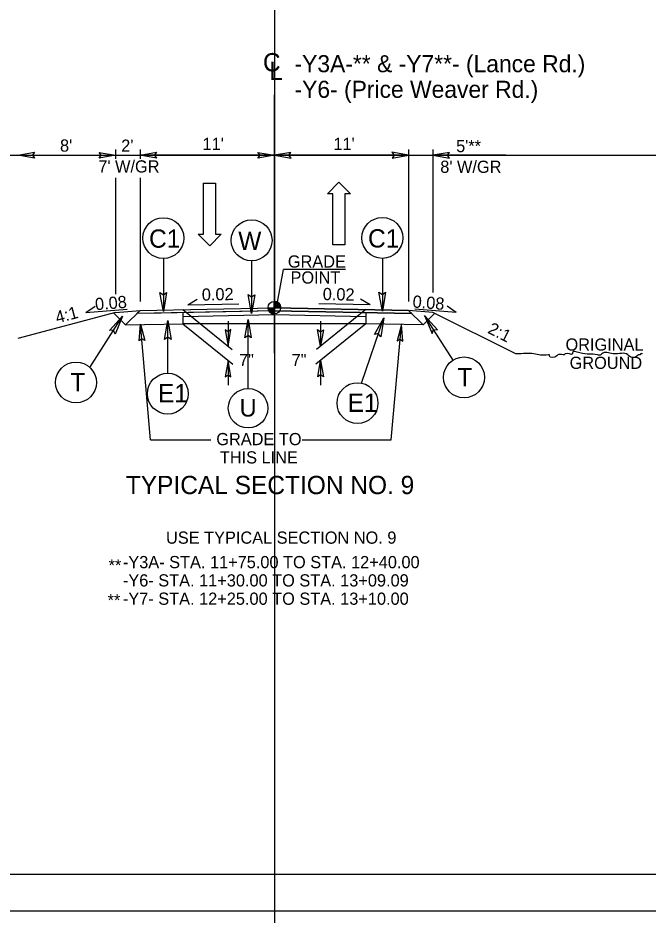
# Model space of a CAD drawing. Extents: x 18938 to 19565, y 6931 to 7973.
# Drawn here: x 19230.5 to 19282.1, y 7371.6 to 7445.2 of the extents above; entities that cross this region are included whole.
import ezdxf

# ---------------------------------------------------------------- set-up
doc = ezdxf.new("R2010")
doc.units = 0
for name, color, linetype in [('Old_Level_11', 7, 'Continuous'), ('Old_Level_2', 7, 'Continuous'), ('Old_Level_3', 7, 'Continuous'), ('Prop Dimension', 7, 'Continuous'), ('Prop Pavement Schedule Description CELL', 7, 'Continuous'), ('Prop Shade Medium', 7, 'Continuous'), ('Prop Terminator CELL', 7, 'Continuous'), ('Sheet Data Field CELL', 7, 'Continuous'), ('Sheet Plot Border Outside CELL', 7, 'Continuous'), ('Sheet Typical CELL', 7, 'Continuous'), ('Typical Curb CELL', 7, 'Continuous'), ('Typical Detail Wedge1 CELL', 7, 'Continuous'), ('Typical Detail Wedge2 CELL', 7, 'Continuous'), ('Typical Detail Wedge3 CELL', 7, 'Continuous'), ('Typical Guardrail CELL', 7, 'Continuous'), ('Typical Hinge Slope Arterial CELL', 7, 'Continuous'), ('Typical ID Circle CELL', 7, 'Continuous'), ('Typical Pavement Slope Information CELL', 7, 'Continuous'), ('Typical Shoulder Slope Information CELL', 7, 'Continuous'), ('Typical Terminator CELL', 7, 'Continuous'), ('Typical Text General CELL', 7, 'Continuous'), ('Typical Text Grade Point CELL', 7, 'Continuous'), ('Typical Text ID Circle CELL', 7, 'Continuous'), ('Typical Text Label CELL', 7, 'Continuous')]:
    doc.layers.add(name, color=color, linetype=linetype)

msp = doc.modelspace()

# ---------------------------------------------------------------- linework, layer by layer
at = {"layer": 'Old_Level_3'}
msp.add_line((19238.512, 7433.94), (19240.512, 7433.94), dxfattribs=at)
at = {"layer": 'Prop Dimension'}
msp.add_lwpolyline([(19155.167, 7371.975), (19382.434, 7371.975), (19382.434, 7518.408), (19155.167, 7518.408)], close=True, dxfattribs=at)
at = {"layer": 'Prop Pavement Schedule Description CELL'}
for p, q in [((19240.512, 7421.215), (19251.513, 7421.435)), ((19262.512, 7421.215), (19251.512, 7421.435)), ((19239.322, 7420.024), (19238.338, 7421.008)), ((19238.512, 7421.055), (19240.512, 7421.215)), ((19239.322, 7420.024), (19240.512, 7421.215)), ((19251.513, 7421.185), (19240.257, 7420.96)), ((19251.513, 7421.185), (19262.767, 7420.96)), ((19264.512, 7421.055), (19262.512, 7421.215)), ((19263.703, 7420.024), (19262.512, 7421.215)), ((19263.703, 7420.024), (19264.66, 7420.981)), ((19271.314, 7417.654), (19264.512, 7421.055)), ((19239.322, 7420.024), (19244.012, 7420.118)), ((19244.012, 7420.122), (19244.012, 7420.118)), ((19259.012, 7420.122), (19259.012, 7420.118)), ((19263.703, 7420.024), (19259.012, 7420.118))]:
    msp.add_line(p, q, dxfattribs=at)
at = {"layer": 'Prop Shade Medium'}
msp.add_line((19238.512, 7421.055), (19230.512, 7418.906), dxfattribs=at)
at = {"layer": 'Sheet Data Field CELL'}
for points in [[(19231.862, 7433.707), (19230.512, 7433.94), (19231.87, 7434.18), (19231.697, 7433.94)], [(19237.162, 7434.172), (19238.512, 7433.94), (19237.155, 7433.7), (19237.327, 7433.94)], [(19237.162, 7434.172), (19238.512, 7433.94), (19237.155, 7433.7), (19237.327, 7433.94)], [(19241.862, 7433.707), (19240.512, 7433.94), (19241.87, 7434.18), (19241.697, 7433.94)], [(19250.177, 7434.172), (19251.527, 7433.94), (19250.17, 7433.7), (19250.342, 7433.94)], [(19252.877, 7434.172), (19251.527, 7433.94), (19252.885, 7433.7), (19252.712, 7433.94)], [(19261.162, 7433.707), (19262.512, 7433.94), (19261.155, 7434.18), (19261.327, 7433.94)], [(19265.862, 7434.172), (19264.512, 7433.94), (19265.87, 7433.7), (19265.697, 7433.94)], [(19240.43, 7418.711), (19240.546, 7420.076), (19240.902, 7418.744), (19240.648, 7418.895)], [(19262.038, 7418.684), (19261.924, 7420.049), (19261.567, 7418.718), (19261.821, 7418.869)], [(19247.49, 7419.634), (19247.722, 7418.284), (19247.962, 7419.642), (19247.722, 7419.469)], [(19255.535, 7419.634), (19255.303, 7418.284), (19255.063, 7419.642), (19255.303, 7419.469)], [(19255.535, 7419.634), (19255.303, 7418.284), (19255.063, 7419.642), (19255.303, 7419.469)], [(19247.954, 7415.768), (19247.721, 7417.118), (19247.481, 7415.76), (19247.721, 7415.933)], [(19255.071, 7415.768), (19255.303, 7417.118), (19255.543, 7415.76), (19255.303, 7415.933)], [(19255.071, 7415.768), (19255.303, 7417.118), (19255.543, 7415.76), (19255.303, 7415.933)]]:
    msp.add_lwpolyline(points, close=True, dxfattribs=at)
at = {"layer": 'Sheet Typical CELL'}
for p, q in [((19230.512, 7433.94), (19238.512, 7433.94)), ((19238.512, 7434.4), (19238.512, 7433.64)), ((19240.512, 7434.4), (19240.512, 7433.64)), ((19262.512, 7433.94), (19240.512, 7433.94)), ((19262.512, 7434.4), (19262.512, 7421.955)), ((19264.512, 7434.4), (19264.512, 7422.672)), ((19270.482, 7433.94), (19264.512, 7433.94)), ((19238.512, 7432.078), (19238.512, 7422.554)), ((19240.512, 7432.086), (19240.512, 7421.955)), ((19244.013, 7421.289), (19248.068, 7418.004)), ((19259.012, 7421.289), (19254.957, 7418.004)), ((19259.012, 7421.289), (19254.957, 7418.004)), ((19241.365, 7410.59), (19240.546, 7420.076)), ((19244.013, 7420.122), (19248.118, 7416.797)), ((19247.722, 7420.328), (19247.722, 7418.284)), ((19259.012, 7420.122), (19254.907, 7416.797)), ((19259.012, 7420.122), (19254.907, 7416.797)), ((19255.303, 7420.328), (19255.303, 7418.284)), ((19255.303, 7420.328), (19255.303, 7418.284)), ((19261.097, 7410.59), (19261.924, 7420.049)), ((19247.721, 7417.118), (19247.721, 7415.094)), ((19255.303, 7417.118), (19255.303, 7415.094)), ((19255.303, 7417.118), (19255.303, 7415.094)), ((19241.365, 7410.59), (19246.325, 7410.59)), ((19253.803, 7410.59), (19261.097, 7410.59))]:
    msp.add_line(p, q, dxfattribs=at)
at = {"layer": 'Typical Curb CELL'}
msp.add_spline([(19281.678, 7417.654), (19281.506, 7417.654), (19281.506, 7417.568), (19281.335, 7417.568), (19281.25, 7417.483), (19280.564, 7417.483), (19280.479, 7417.568), (19279.279, 7417.654), (19278.337, 7417.654), (19278.252, 7417.568), (19277.995, 7417.568), (19276.539, 7417.74), (19275.939, 7417.74), (19275.939, 7417.654), (19275.34, 7417.654), (19275.254, 7417.568), (19275.168, 7417.568), (19274.74, 7417.568), (19274.654, 7417.483), (19274.055, 7417.483), (19274.055, 7417.568), (19273.969, 7417.568), (19272.77, 7417.654), (19271.399, 7417.654), (19271.314, 7417.654)], degree=3, dxfattribs=at)
at = {"layer": 'Typical Detail Wedge1 CELL'}
for p, q in [((19251, 7421.435), (19251.513, 7421.435)), ((19251.512, 7420.922), (19251.513, 7421.435)), ((19251.513, 7421.435), (19251.512, 7420.922)), ((19251.513, 7421.435), (19251.513, 7421.946)), ((19252.024, 7421.435), (19251.513, 7421.435))]:
    msp.add_line(p, q, dxfattribs=at)
for points in [[(19251.003, 7421.435), (19251.003, 7421.379)], [(19251.014, 7421.435), (19251.014, 7421.319)], [(19251.024, 7421.435), (19251.024, 7421.281)], [(19251.034, 7421.435), (19251.034, 7421.252)], [(19251.044, 7421.435), (19251.044, 7421.227)], [(19251.054, 7421.435), (19251.054, 7421.205)], [(19251.065, 7421.435), (19251.065, 7421.186)], [(19251.075, 7421.435), (19251.075, 7421.168)], [(19251.085, 7421.435), (19251.085, 7421.152)], [(19251.096, 7421.435), (19251.096, 7421.137)], [(19251.106, 7421.435), (19251.106, 7421.124)], [(19251.116, 7421.435), (19251.116, 7421.111)], [(19251.126, 7421.435), (19251.126, 7421.098)], [(19251.137, 7421.435), (19251.137, 7421.087)], [(19251.147, 7421.435), (19251.147, 7421.076)], [(19251.157, 7421.435), (19251.157, 7421.066)], [(19251.167, 7421.435), (19251.167, 7421.056)], [(19251.178, 7421.435), (19251.177, 7421.047)], [(19251.188, 7421.435), (19251.188, 7421.039)], [(19251.198, 7421.435), (19251.198, 7421.03)], [(19251.208, 7421.435), (19251.208, 7421.023)], [(19251.218, 7421.435), (19251.218, 7421.015)], [(19251.229, 7421.435), (19251.228, 7421.008)], [(19251.239, 7421.435), (19251.239, 7421.002)], [(19251.249, 7421.435), (19251.249, 7420.995)], [(19251.259, 7421.435), (19251.259, 7420.989)], [(19251.269, 7421.435), (19251.269, 7420.984)], [(19251.28, 7421.435), (19251.28, 7420.978)], [(19251.29, 7421.435), (19251.29, 7420.973)], [(19251.301, 7421.435), (19251.3, 7420.969)], [(19251.311, 7421.435), (19251.311, 7420.964)], [(19251.321, 7421.435), (19251.321, 7420.96)], [(19251.331, 7421.435), (19251.331, 7420.956)], [(19251.342, 7421.435), (19251.342, 7420.952)], [(19251.352, 7421.435), (19251.352, 7420.948)], [(19251.362, 7421.435), (19251.362, 7420.945)], [(19251.372, 7421.435), (19251.372, 7420.942)], [(19251.382, 7421.435), (19251.382, 7420.939)], [(19251.393, 7421.435), (19251.392, 7420.937)], [(19251.403, 7421.435), (19251.403, 7420.934)], [(19251.413, 7421.435), (19251.413, 7420.932)], [(19251.423, 7421.435), (19251.423, 7420.931)], [(19251.433, 7421.435), (19251.433, 7420.929)], [(19251.444, 7421.435), (19251.444, 7420.927)], [(19251.454, 7421.435), (19251.454, 7420.926)], [(19251.464, 7421.435), (19251.464, 7420.925)], [(19251.474, 7421.435), (19251.474, 7420.924)], [(19251.485, 7421.435), (19251.485, 7420.924)], [(19251.495, 7421.435), (19251.495, 7420.923)], [(19251.505, 7421.435), (19251.505, 7420.922), (19251.505, 7420.922)], [(19251.517, 7421.946), (19251.517, 7421.946), (19251.517, 7421.435)], [(19251.528, 7421.946), (19251.528, 7421.435)], [(19251.538, 7421.946), (19251.538, 7421.435)], [(19251.548, 7421.945), (19251.548, 7421.435)], [(19251.558, 7421.944), (19251.558, 7421.435)], [(19251.569, 7421.943), (19251.569, 7421.435)], [(19251.579, 7421.942), (19251.579, 7421.435)], [(19251.589, 7421.941), (19251.589, 7421.435)], [(19251.6, 7421.939), (19251.599, 7421.435)], [(19251.61, 7421.937), (19251.61, 7421.435)], [(19251.62, 7421.935), (19251.62, 7421.435)], [(19251.63, 7421.933), (19251.63, 7421.435)], [(19251.641, 7421.93), (19251.64, 7421.435)], [(19251.651, 7421.927), (19251.651, 7421.435)], [(19251.661, 7421.924), (19251.661, 7421.435)], [(19251.671, 7421.921), (19251.671, 7421.435)], [(19251.682, 7421.918), (19251.681, 7421.435)], [(19251.692, 7421.914), (19251.691, 7421.435)], [(19251.702, 7421.91), (19251.702, 7421.435)], [(19251.712, 7421.906), (19251.712, 7421.435)], [(19251.722, 7421.901), (19251.722, 7421.435)], [(19251.732, 7421.897), (19251.732, 7421.435)], [(19251.743, 7421.892), (19251.743, 7421.435)], [(19251.753, 7421.886), (19251.753, 7421.435)], [(19251.763, 7421.881), (19251.763, 7421.435)], [(19251.773, 7421.875), (19251.773, 7421.435)], [(19251.784, 7421.869), (19251.784, 7421.435)], [(19251.794, 7421.862), (19251.794, 7421.435)], [(19251.804, 7421.855), (19251.804, 7421.435)], [(19251.815, 7421.848), (19251.815, 7421.435)], [(19251.825, 7421.84), (19251.825, 7421.435)], [(19251.835, 7421.832), (19251.835, 7421.435)], [(19251.845, 7421.824), (19251.845, 7421.435)], [(19251.856, 7421.814), (19251.855, 7421.434)], [(19251.866, 7421.805), (19251.866, 7421.435)], [(19251.876, 7421.795), (19251.876, 7421.434)], [(19251.886, 7421.784), (19251.886, 7421.434)], [(19251.896, 7421.773), (19251.896, 7421.435)], [(19251.907, 7421.761), (19251.906, 7421.434)], [(19251.917, 7421.748), (19251.917, 7421.434)], [(19251.927, 7421.735), (19251.927, 7421.435)], [(19251.937, 7421.72), (19251.937, 7421.434)], [(19251.948, 7421.704), (19251.948, 7421.434)], [(19251.958, 7421.687), (19251.958, 7421.435)], [(19251.968, 7421.668), (19251.968, 7421.434)], [(19251.978, 7421.647), (19251.978, 7421.434)], [(19251.989, 7421.623), (19251.989, 7421.435)], [(19251.999, 7421.594), (19251.999, 7421.434)], [(19252.009, 7421.559), (19252.009, 7421.434)], [(19252.019, 7421.507), (19252.019, 7421.435)]]:
    msp.add_lwpolyline(points, dxfattribs=at)
msp.add_circle((19251.512, 7421.434), 0.512, dxfattribs=at)
for start, end in [(179.99048, 269.99048), (359.99048, 89.99048)]:
    msp.add_arc((19251.512, 7421.434), 0.512, start, end, dxfattribs=at)
at = {"layer": 'Typical Detail Wedge3 CELL'}
for p, q in [((19245.719, 7427.453), (19245.719, 7431.653)), ((19245.719, 7431.653), (19246.709, 7431.653)), ((19246.709, 7431.653), (19246.709, 7427.453)), ((19255.865, 7430.782), (19256.795, 7431.727)), ((19256.795, 7431.727), (19257.755, 7430.782)), ((19256.315, 7430.782), (19255.865, 7430.782)), ((19256.315, 7426.582), (19256.315, 7430.782)), ((19257.755, 7430.782), (19257.305, 7430.782)), ((19257.305, 7430.782), (19257.305, 7426.582)), ((19246.229, 7426.508), (19245.269, 7427.453)), ((19245.269, 7427.453), (19245.719, 7427.453)), ((19247.159, 7427.453), (19246.229, 7426.508)), ((19246.709, 7427.453), (19247.159, 7427.453)), ((19257.305, 7426.582), (19256.315, 7426.582))]:
    msp.add_line(p, q, dxfattribs=at)
at = {"layer": 'Typical Guardrail CELL'}
for p, q in [((19251.527, 7635.457), (19251.527, 7289.252)), ((19202.089, 7433.94), (19329.987, 7433.94))]:
    msp.add_line(p, q, dxfattribs=at)
at = {"layer": 'Typical Hinge Slope Arterial CELL'}
for p, q in [((19240.512, 7421.215), (19251.513, 7421.435)), ((19251.513, 7421.435), (19262.512, 7421.215)), ((19240.257, 7420.96), (19240.512, 7421.215)), ((19242.257, 7421), (19240.257, 7420.96)), ((19251.513, 7421.185), (19242.257, 7421)), ((19242.257, 7421), (19242.257, 7421)), ((19262.767, 7420.96), (19251.513, 7421.185)), ((19262.512, 7421.215), (19262.767, 7420.96))]:
    msp.add_line(p, q, dxfattribs=at)
at = {"layer": 'Typical ID Circle CELL'}
for p, q in [((19244.012, 7421.035), (19244.012, 7420.122)), ((19244.012, 7420.716), (19251.512, 7420.866)), ((19251.512, 7420.866), (19259.012, 7420.716)), ((19259.012, 7421.035), (19259.012, 7420.122)), ((19259.012, 7420.122), (19244.012, 7420.122))]:
    msp.add_line(p, q, dxfattribs=at)
at = {"layer": 'Typical Pavement Slope Information CELL'}
msp.add_lwpolyline([(19380.142, 7515.401), (19177.642, 7515.401), (19177.642, 7374.986), (19380.142, 7374.986)], close=True, dxfattribs=at)
at = {"layer": 'Typical Terminator CELL'}
for p, q in [((19242.425, 7425.465), (19242.425, 7421.134)), ((19249.655, 7425.282), (19249.655, 7420.951)), ((19260.365, 7425.483), (19260.365, 7421.152)), ((19236.397, 7416.545), (19239.068, 7420.739)), ((19258.658, 7415.253), (19260.473, 7420.614)), ((19266.154, 7417.134), (19263.828, 7420.787)), ((19242.788, 7416.061), (19242.788, 7420.392)), ((19249.362, 7414.815), (19249.362, 7420.464))]:
    msp.add_line(p, q, dxfattribs=at)
for centre, radius in [((19242.425, 7427.141), 1.676), ((19260.365, 7427.159), 1.676), ((19249.655, 7426.958), 1.676), ((19235.269, 7415.306), 1.676), ((19267.055, 7415.72), 1.676), ((19242.788, 7414.386), 1.676), ((19249.362, 7413.196), 1.619), ((19258.33, 7413.609), 1.676)]:
    msp.add_circle(centre, radius, dxfattribs=at)
at = {"layer": 'Typical Text General CELL'}
for points in [[(19242.692, 7422.686), (19242.425, 7421.134), (19242.149, 7422.694), (19242.425, 7422.496)], [(19249.922, 7422.503), (19249.655, 7420.951), (19249.379, 7422.511), (19249.655, 7422.313)], [(19260.633, 7422.704), (19260.365, 7421.152), (19260.09, 7422.712), (19260.365, 7422.514)], [(19238.009, 7419.574), (19239.068, 7420.739), (19238.463, 7419.275), (19238.337, 7419.59)], [(19259.722, 7419.23), (19260.473, 7420.614), (19260.234, 7419.047), (19260.036, 7419.324)], [(19264.887, 7419.622), (19263.828, 7420.787), (19264.433, 7419.323), (19264.56, 7419.638)], [(19242.52, 7418.841), (19242.788, 7420.392), (19243.064, 7418.832), (19242.788, 7419.03)], [(19249.103, 7418.965), (19249.362, 7420.464), (19249.628, 7418.957), (19249.362, 7419.148)]]:
    msp.add_lwpolyline(points, close=True, dxfattribs=at)
at = {"layer": 'Typical Text Grade Point CELL'}
for p, q in [((19244.417, 7421.675), (19245.2, 7422.148)), ((19259.361, 7421.675), (19258.578, 7422.148)), ((19236.08, 7421.035), (19236.833, 7421.554)), ((19236.08, 7421.035), (19239.466, 7421.306)), ((19244.417, 7421.675), (19248.605, 7421.759)), ((19259.361, 7421.675), (19255.172, 7421.759)), ((19266.418, 7421.043), (19263.032, 7421.314)), ((19266.418, 7421.043), (19265.665, 7421.562))]:
    msp.add_line(p, q, dxfattribs=at)
at = {"layer": 'Typical Text ID Circle CELL'}
for p, q in [((19251.512, 7438.876), (19251.512, 7433.94)), ((19251.512, 7433.94), (19251.512, 7417.698)), ((19251.762, 7421.888), (19252.258, 7424.556)), ((19257.335, 7424.555), (19252.258, 7424.556))]:
    msp.add_line(p, q, dxfattribs=at)

# ---------------------------------------------------------------- texts
at = {"layer": 'Old_Level_11'}
for s, height, p in [('TYPICAL SECTION NO. 9', 1.5, (19239.35, 7406.15)), ('USE TYPICAL SECTION NO. 9', 1, (19242.643, 7402.086))]:
    msp.add_text(s, height=height, dxfattribs=at).set_placement(p)
at = {"layer": 'Old_Level_2'}
for s, p in [('ORIGINAL', (19275.37, 7417.917)), ('GROUND', (19275.707, 7416.417))]:
    msp.add_text(s, height=1, dxfattribs=at).set_placement(p)
at = {"layer": 'Prop Terminator CELL'}
for s, height, p in [('C1', 1.5, (19241.251, 7426.352)), ('W', 1.5, (19248.561, 7426.169)), ('C1', 1.5, (19259.192, 7426.37)), ('T', 1.5, (19266.51, 7415)), ('E1', 1.5, (19241.98, 7413.674)), ('U', 1.449, (19248.666, 7412.509)), ('E1', 1.5, (19257.521, 7412.898))]:
    msp.add_text(s, height=height, dxfattribs=at).set_placement(p)
msp.add_text('T', height=1.5, rotation=360, dxfattribs=at).set_placement((19234.8, 7414.586))
at = {"layer": 'Sheet Plot Border Outside CELL'}
for s, p in [('GRADE', (19252.623, 7424.724)), ('POINT', (19252.841, 7423.413))]:
    msp.add_text(s, height=1, rotation=0.00004, dxfattribs=at).set_placement(p)
at = {"layer": 'Typical Detail Wedge2 CELL'}
for s, p in [("11'", (19245.633, 7434.368)), ("11'", (19256.357, 7434.368)), ("8'", (19233.958, 7434.229)), ("2'", (19238.973, 7434.219)), ("5'**", (19266.411, 7434.19)), ("7' W/GR", (19237.097, 7432.519)), ("8' W/GR", (19265.111, 7432.49)), ('7"', (19248.624, 7416.645)), ('GRADE TO', (19246.762, 7410.164)), ('THIS LINE', (19247.053, 7408.664)), ('**', (19237.939, 7399.816)), ('-Y3A- STA. 11+75.00 TO STA. 12+40.00', (19239.111, 7400.079)), ('-Y6- STA. 11+30.00 TO STA. 13+09.09', (19239.111, 7398.579)), ('**', (19237.859, 7396.955)), ('-Y7- STA. 12+25.00 TO STA. 13+10.00', (19239.111, 7397.079))]:
    msp.add_text(s, height=1, dxfattribs=at).set_placement(p)
msp.add_text('7"', height=1, rotation=360, dxfattribs=at).set_placement((19252.935, 7416.645))
msp.add_text('7"', height=1, rotation=360, dxfattribs=at).set_placement((19252.935, 7416.645))
at = {"layer": 'Typical Shoulder Slope Information CELL'}
for s, rotation, p in [('4:1', 15.1346, (19233.728, 7420.131)), ('2:1', 333.43491, (19268.925, 7419.393))]:
    msp.add_text(s, height=1, rotation=rotation, dxfattribs=at).set_placement(p)
at = {"layer": 'Typical Text Grade Point CELL'}
for s, rotation, p in [('0.02', 1.14574, (19245.584, 7422.01)), ('0.02', 358.85426, (19255.476, 7422.064)), ('0.08', 4.5738, (19236.868, 7421.224)), ('0.08', 355.4262, (19262.814, 7421.457))]:
    msp.add_text(s, height=1, rotation=rotation, dxfattribs=at).set_placement(p)
at = {"layer": 'Typical Text Label CELL'}
for s, height, p in [('C', 1.5, (19250.583, 7440.811)), ('-Y3A-** & -Y7**- (Lance Rd.)', 1.4, (19253.168, 7440.741)), ('L', 1.5, (19251.1, 7440.104)), ('-Y6- (Price Weaver Rd.)', 1.4, (19253.168, 7438.641))]:
    msp.add_text(s, height=height, dxfattribs=at).set_placement(p)

doc.saveas('drawing.dxf')
